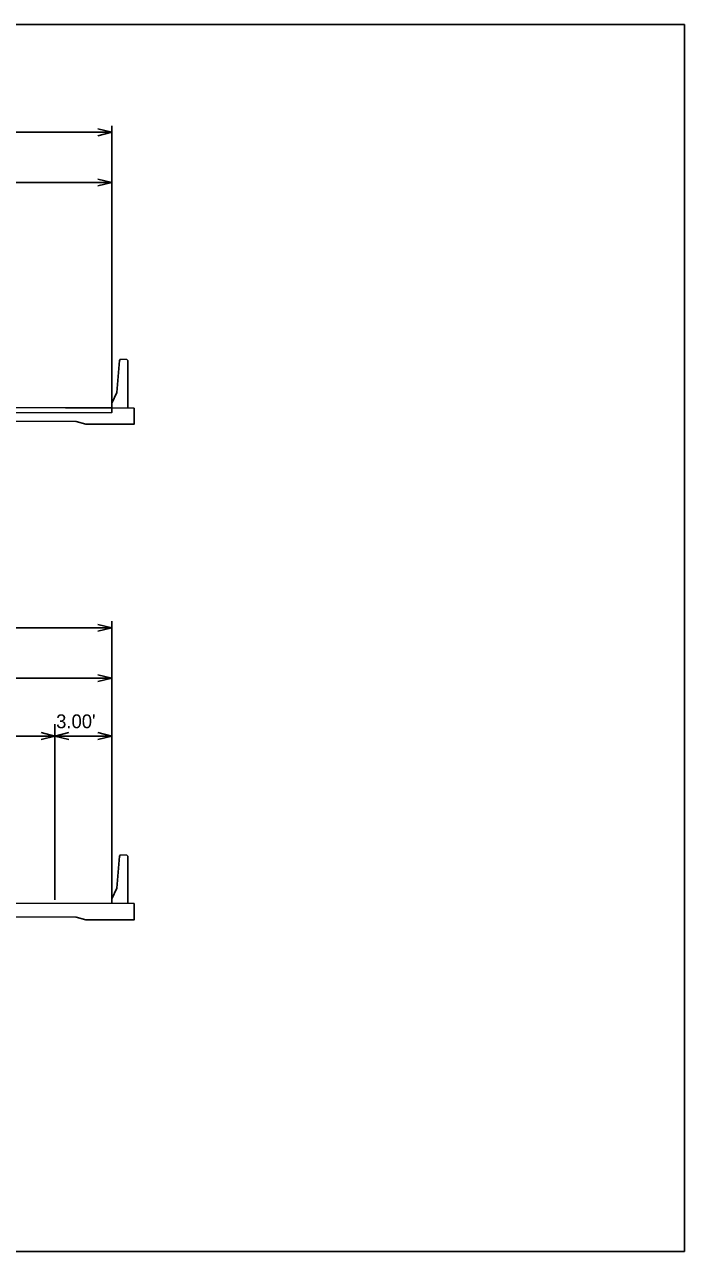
# Model space of a CAD drawing. Extents: x 8410 to 81668, y 7924 to 12712.
# Drawn here: x 15781 to 16868, y 7924 to 9944 of the extents above; entities that cross this region are included whole.
import ezdxf

# ---------------------------------------------------------------- set-up
doc = ezdxf.new("R2010")
doc.units = 0
for name, color, linetype in [('Level 2', 7, 'Continuous'), ('Level 3', 7, 'Continuous'), ('SheetBorder', 7, 'Continuous')]:
    doc.layers.add(name, color=color, linetype=linetype)

msp = doc.modelspace()

# ---------------------------------------------------------------- linework, layer by layer
at = {"layer": 'Level 2'}
for p, q in [((15924.3, 9312.7), (15924.3, 9777.5)), ((14675.7, 9766.6), (15924.3, 9766.6)), ((15362.5, 9683.9), (15924.3, 9683.9)), ((15937.1, 9391), (15932.9, 9338)), ((15938.5, 9392.9), (15937.1, 9391)), ((15949.3, 9392.6), (15938.5, 9392.9)), ((15950.7, 9390.7), (15949.3, 9392.6)), ((15950.7, 9312.7), (15950.7, 9390.7)), ((15932.9, 9338), (15924.4, 9320.7)), ((15924.4, 9320.7), (15924.3, 9312.7)), ((15865.5, 9290.3), (15300, 9293.3)), ((15881.8, 9285.9), (15865.5, 9290.3)), ((14675.7, 8950.7), (15924.3, 8950.7)), ((15924.3, 8496.8), (15924.3, 8961.6)), ((15362.5, 8868), (15924.3, 8868)), ((15830.7, 8502.9), (15830.7, 8792.1)), ((15456.1, 8772.6), (15830.7, 8772.6)), ((15924.3, 8772.6), (15830.7, 8772.6)), ((15937.1, 8575.1), (15932.9, 8522)), ((15938.5, 8576.9), (15937.1, 8575.1)), ((15949.3, 8576.7), (15938.5, 8576.9)), ((15950.7, 8574.8), (15949.3, 8576.7)), ((15950.7, 8496.7), (15950.7, 8574.8)), ((15924.4, 8504.7), (15924.3, 8496.8)), ((15932.9, 8522), (15924.4, 8504.7)), ((15865.5, 8474.4), (15300, 8477.3)), ((15881.8, 8469.9), (15865.5, 8474.4))]:
    msp.add_line(p, q, dxfattribs=at)
for points in [[(15901.6, 9772.3), (15924.3, 9766.6), (15901.6, 9760.9)], [(15901.6, 9689.6), (15924.3, 9683.9), (15901.6, 9678.2)], [(15961.2, 9312.6), (15961.2, 9285.9), (15881.8, 9285.9)], [(15901.6, 8956.3), (15924.3, 8950.7), (15901.6, 8945)], [(15901.6, 8873.6), (15924.3, 8868), (15901.6, 8862.3)], [(15808, 8766.9), (15830.7, 8772.6), (15808, 8778.2)], [(15853.4, 8766.9), (15830.7, 8772.6), (15853.4, 8778.2)], [(15901.6, 8766.9), (15924.3, 8772.6), (15901.6, 8778.2)], [(15961.2, 8496.7), (15961.2, 8469.9), (15881.8, 8469.9)]]:
    msp.add_lwpolyline(points, dxfattribs=at)
at = {"layer": 'Level 3'}
for p, q in [((15362.5, 9314.4), (15961.2, 9312.6)), ((15362.5, 8498.4), (15961.2, 8496.7))]:
    msp.add_line(p, q, dxfattribs=at)
msp.add_lwpolyline([(15730.5, 9313.3), (15924.3, 9312.7), (15924.3, 9305.1), (15728.3, 9304.6)], dxfattribs=at)
at = {"layer": 'SheetBorder'}
msp.add_lwpolyline([(13732.5, 9944), (16867.5, 9944), (16867.5, 7924), (13732.5, 7924)], close=True, dxfattribs=at)

# ---------------------------------------------------------------- texts
at = {"layer": 'Level 2'}
msp.add_text("3.00'", height=22.71, dxfattribs=at).set_placement((15832.7, 8785.5))

doc.saveas('drawing.dxf')
